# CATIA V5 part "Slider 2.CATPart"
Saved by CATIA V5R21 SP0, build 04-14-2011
Part number: Part 3
Bounding box of the stored display mesh (mm): x 0 to 20, y -5 to 5, z -5 to 5
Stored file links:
  D:\CATIA V5R21 E-RESOURCES\CATIA-V5R21\catia-v5r21-prt\c16-catia-v5r20-prt\Cable Joint - (Fig16-60)\CAT_V5R21_Slider 2.CATPart
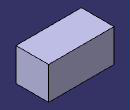
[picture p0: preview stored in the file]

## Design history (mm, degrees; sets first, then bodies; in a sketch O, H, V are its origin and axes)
Body1 (main body)
  Sketch1 on yz-plane, origin (0, 0, 0), H (0, 1, 0), V (0, 0, 1)
    line L1 (5, 5) -> (5, -5)
    line L2 (5, -5) -> (-5, -5)
    line L3 (-5, -5) -> (-5, 5)
    line L4 (-5, 5) -> (5, 5)
    length L4 = 10
    length L1 = 10
    vertical: L1 V, L3 V
    horizontal: L2 H, L4 H
    equidistance: L1 L3 O, L2 L4 O
  Pad1: profile Sketch1, direction (1, 0, 0), length 20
